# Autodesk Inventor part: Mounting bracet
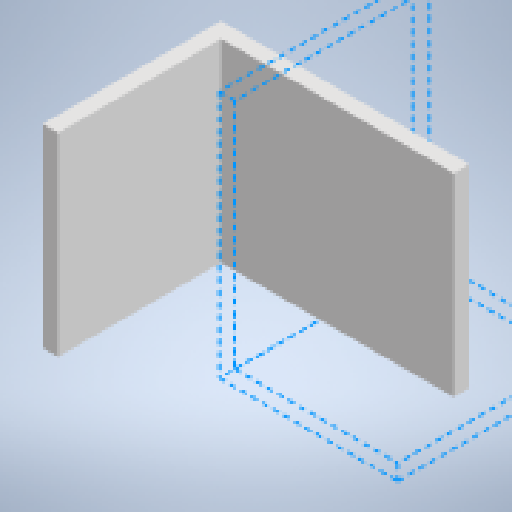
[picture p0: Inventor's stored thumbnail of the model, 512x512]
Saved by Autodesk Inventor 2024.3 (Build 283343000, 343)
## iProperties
Created: 2024-12
Part Number: Mounting bracet
Material: Generic
Document SubType Name: Modeling
Designer: ruhr
Density: 1 g/cm^3
Appearance: Default
Author: ruhr
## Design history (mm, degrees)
workplane "Work Plane1"
sketch "Sketch1"
  geometry: L1 (30, 25)-(-30, 25); L2 (-30, 25)-(-30, -25); L3 (-30, -25)-(30, -25); L4 (30, -25)-(30, 25); L5 (30, 25)-(-30, -25); L6 (-30, 25)-(30, -25); 1 further point
  constraints: 12 end point, 2 midpoint, 2 parallel, 1 horizontal, 1 perpendicular
  dimensions: "d0" = 60 distance of L3.end L2.end; "d1" = 50 distance of L2.end L1.end
extrude "Extrusion1" new body sketch "Sketch1" distance "d2" = 4; taper "d3" = 0 deg
sketch "Sketch2"
  geometry: L1 (-30, 25)-(-30, -25) reference; L2 (-30, 25)-(-34, 25); L3 (-34, 25)-(-34, -25); L4 (-34, -25)-(-30, -25); L5 (-30, -25)-(-30, 25); 2 further points
  constraints: 8 end point, 2 parallel, 1 horizontal, 1 perpendicular
  dimensions: "d4" = 4 distance of L4.end L3.end
extrude "Extrusion2" join sketch "Sketch2" distance "d5" = 42; taper "d7" = 0 deg; dims "d6" = 4, "d8" = 0
body "Solid1"
